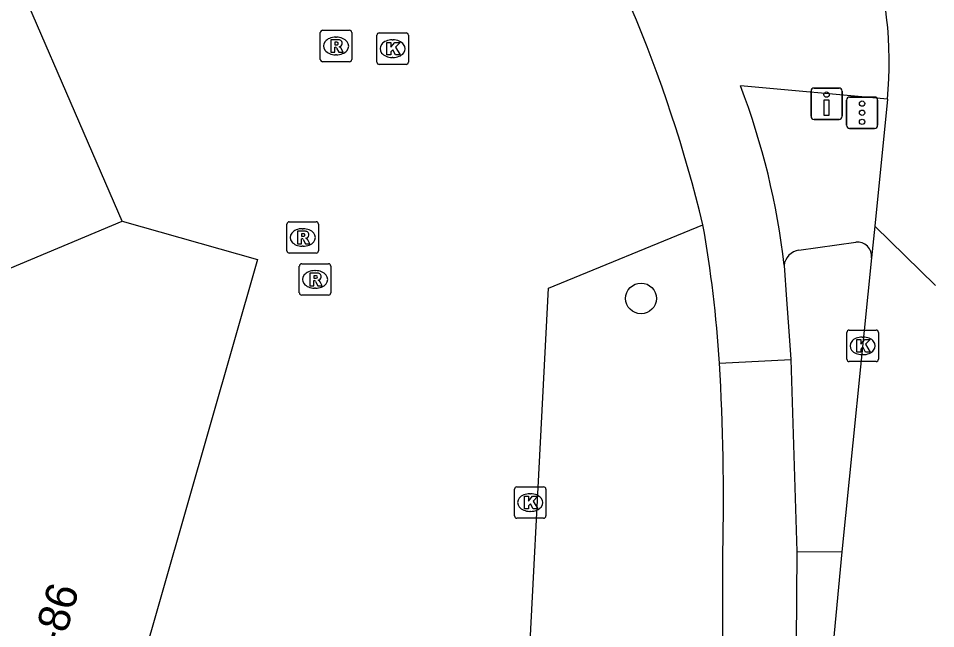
# Model space of a CAD drawing. Extents: x 162542 to 163144, y 380786 to 381511.
# Drawn here: x 163114.67 to 163143.84, y 381201.72 to 381221.15 of the extents above; entities that cross this region are included whole.
import ezdxf

# ---------------------------------------------------------------- set-up
doc = ezdxf.new("R2010")
doc.units = 0
for name, color, linetype in [('IMGEO_Boom', 7, 'Continuous'), ('IMGEO_Drukknoppaal', 7, 'Continuous'), ('IMGEO_Fietspad_gesloten', 7, 'Continuous'), ('IMGEO_Fietspad_open', 7, 'Continuous'), ('IMGEO_Kolk', 7, 'Continuous'), ('IMGEO_Pand', 7, 'Continuous'), ('IMGEO_Pand_nummerreeks', 7, 'Continuous'), ('IMGEO_Rijbaan_lokaal_gesloten', 7, 'Continuous'), ('IMGEO_Rioolput', 7, 'Continuous'), ('IMGEO_Verkeerseiland_open', 7, 'Continuous'), ('IMGEO_Verkeersregelinstallatiepaal', 7, 'Continuous'), ('IMGEO_Voetpad_open', 7, 'Continuous')]:
    doc.layers.add(name, color=color, linetype=linetype)

msp = doc.modelspace()

# ---------------------------------------------------------------- linework, layer by layer
at = {"layer": 'IMGEO_Boom'}
msp.add_circle((163134.469, 381212.234), 0.489, dxfattribs=at)
at = {"layer": 'IMGEO_Drukknoppaal'}
for p, q in [((163139.976, 381218.931), (163140.766, 381218.931)), ((163140.766, 381218.931), (163139.976, 381218.931)), ((163139.876, 381218.031), (163139.876, 381218.831)), ((163139.876, 381218.831), (163139.876, 381218.031)), ((163140.866, 381218.831), (163140.866, 381218.031)), ((163140.866, 381218.031), (163140.866, 381218.831)), ((163140.766, 381217.931), (163139.976, 381217.931)), ((163139.976, 381217.931), (163140.766, 381217.931))]:
    msp.add_line(p, q, dxfattribs=at)
msp.add_lwpolyline([(163140.446, 381218.556), (163140.446, 381218.056), (163140.296, 381218.056), (163140.296, 381218.556), (163140.446, 381218.556)], dxfattribs=at)
msp.add_circle((163140.371, 381218.721), 0.085, dxfattribs=at)
for centre, start, end in [((163139.976, 381218.831), 90, 180), ((163139.976, 381218.831), 90, 180), ((163140.766, 381218.831), 0, 90), ((163140.766, 381218.831), 360, 90), ((163139.976, 381218.031), 180, 270), ((163139.976, 381218.031), 180, 270), ((163140.766, 381218.031), 270, 0), ((163140.766, 381218.031), 270, 0)]:
    msp.add_arc(centre, 0.1, start, end, dxfattribs=at)
at = {"layer": 'IMGEO_Fietspad_gesloten'}
for points in [[(163142.306, 381218.573), (163137.629, 381218.999)], [(163139.017, 381213.288), (163139.096, 381212.197), (163139.171, 381211.191), (163139.237, 381210.292)], [(163136.964, 381210.179), (163139.237, 381210.292)]]:
    msp.add_lwpolyline(points, dxfattribs=at)
for centre, radius, start, end in [((163093.253, 381204.128), 44.432, 13.6085, 32.4494), ((163116.281, 381210.787), 22.873, 6.2787, 21.0419), ((163096.562, 381207.585), 40.485, 3.6731, 9.9519)]:
    msp.add_arc(centre, radius, start, end, dxfattribs=at)
at = {"layer": 'IMGEO_Fietspad_open'}
for points in [[(163139.237, 381210.292), (163139.424, 381204.175)], [(163139.424, 381204.175), (163139.38, 381198.374), (163139.259, 381195.134), (163138.982, 381190.545)]]:
    msp.add_lwpolyline(points, dxfattribs=at)
for centre, radius, start, end in [((163067.009, 381205.966), 70.081, 358.54095, 3.4461), ((162956.403, 381202.847), 180.67, 357.8353, 0.42328)]:
    msp.add_arc(centre, radius, start, end, dxfattribs=at)
at = {"layer": 'IMGEO_Kolk'}
for p, q in [((163126.144, 381220.684), (163126.996, 381220.684)), ((163126.069, 381219.758), (163126.069, 381220.61)), ((163126.557, 381220.464), (163126.582, 381220.464)), ((163127.07, 381220.61), (163127.07, 381219.758)), ((163126.58, 381219.904), (163126.555, 381219.904)), ((163126.996, 381219.684), (163126.144, 381219.684)), ((163141.016, 381210.3), (163141.016, 381211.152)), ((163141.091, 381211.226), (163141.943, 381211.226)), ((163141.504, 381211.006), (163141.529, 381211.006)), ((163142.017, 381211.152), (163142.017, 381210.3)), ((163141.527, 381210.446), (163141.502, 381210.446)), ((163141.943, 381210.226), (163141.091, 381210.226)), ((163130.445, 381205.312), (163130.445, 381206.164)), ((163130.52, 381206.238), (163131.372, 381206.238)), ((163131.446, 381206.164), (163131.446, 381205.312)), ((163130.933, 381206.018), (163130.958, 381206.018)), ((163131.372, 381205.238), (163130.52, 381205.238)), ((163130.956, 381205.458), (163130.931, 381205.458))]:
    msp.add_line(p, q, dxfattribs=at)
for points in [[(163126.144, 381220.684), (163126.996, 381220.684)], [(163126.069, 381219.758), (163126.069, 381220.61)], [(163126.39, 381220.384), (163126.513, 381220.384), (163126.513, 381220.233), (163126.643, 381220.384), (163126.807, 381220.384), (163126.661, 381220.233), (163126.814, 381219.984), (163126.662, 381219.984), (163126.577, 381220.148), (163126.513, 381220.081), (163126.513, 381219.984), (163126.39, 381219.984), (163126.39, 381220.384)], [(163127.07, 381220.61), (163127.07, 381219.758)], [(163126.996, 381219.684), (163126.144, 381219.684)], [(163141.016, 381210.3), (163141.016, 381211.152)], [(163141.091, 381211.226), (163141.943, 381211.226)], [(163142.017, 381211.152), (163142.017, 381210.3)], [(163141.337, 381210.926), (163141.46, 381210.926), (163141.46, 381210.775), (163141.59, 381210.926), (163141.754, 381210.926), (163141.608, 381210.775), (163141.761, 381210.526), (163141.609, 381210.526), (163141.524, 381210.69), (163141.46, 381210.623), (163141.46, 381210.526), (163141.337, 381210.526), (163141.337, 381210.926)], [(163141.943, 381210.226), (163141.091, 381210.226)], [(163130.445, 381205.312), (163130.445, 381206.164)], [(163130.52, 381206.238), (163131.372, 381206.238)], [(163131.446, 381206.164), (163131.446, 381205.312)], [(163130.766, 381205.938), (163130.889, 381205.938), (163130.889, 381205.787), (163131.019, 381205.938), (163131.183, 381205.938), (163131.037, 381205.787), (163131.19, 381205.538), (163131.038, 381205.538), (163130.953, 381205.702), (163130.889, 381205.635), (163130.889, 381205.538), (163130.766, 381205.538), (163130.766, 381205.938)], [(163131.372, 381205.238), (163130.52, 381205.238)]]:
    msp.add_lwpolyline(points, dxfattribs=at)
for centre, start, end in [((163126.146, 381220.608), 91.552, 178.448), ((163126.146, 381220.608), 91.552, 178.448), ((163126.994, 381220.608), 1.552, 88.448), ((163126.994, 381220.608), 1.552, 88.448), ((163126.146, 381219.76), 181.552, 268.448), ((163126.146, 381219.76), 181.552, 268.448), ((163126.994, 381219.76), 271.552, 358.448), ((163126.994, 381219.76), 271.552, 358.448), ((163141.093, 381211.15), 91.552, 178.448), ((163141.093, 381211.15), 91.552, 178.448), ((163141.941, 381211.15), 1.552, 88.448), ((163141.941, 381211.15), 1.552, 88.448), ((163141.093, 381210.302), 181.552, 268.448), ((163141.093, 381210.302), 181.552, 268.448), ((163141.941, 381210.302), 271.552, 358.448), ((163141.941, 381210.302), 271.552, 358.448), ((163130.522, 381206.162), 91.552, 178.448), ((163130.522, 381206.162), 91.552, 178.448), ((163131.37, 381206.162), 1.552, 88.448), ((163131.37, 381206.162), 1.552, 88.448), ((163130.522, 381205.314), 181.552, 268.448), ((163130.522, 381205.314), 181.552, 268.448), ((163131.37, 381205.314), 271.552, 358.448), ((163131.37, 381205.314), 271.552, 358.448)]:
    msp.add_arc(centre, 0.0765, start, end, dxfattribs=at)
for centre, major_axis, ratio, start_param, end_param in [((163126.556, 381220.184), (-0.387, 0.002), 0.722429, 4.712389, 7.853982), ((163126.581, 381220.184), (-0.39, 0.002), 0.717154, 1.570796, 4.712389), ((163141.503, 381210.726), (-0.387, 0.002), 0.722429, 4.712389, 7.853982), ((163141.528, 381210.726), (-0.39, 0.002), 0.717154, 1.570796, 4.712389), ((163130.932, 381205.738), (-0.387, 0.002), 0.722429, 4.712389, 7.853982), ((163130.957, 381205.738), (-0.39, 0.002), 0.717154, 1.570796, 4.712389)]:
    msp.add_ellipse(centre, major_axis=major_axis, ratio=ratio, start_param=start_param, end_param=end_param, dxfattribs=at)
at = {"layer": 'IMGEO_Pand'}
for points in [[(163085.066, 381198.411), (163084.14, 381200.482), (163108.916, 381210.892), (163117.973, 381214.696)], [(163117.973, 381214.696), (163122.273, 381213.473), (163115.473, 381189.724)]]:
    msp.add_lwpolyline(points, dxfattribs=at)
at = {"layer": 'IMGEO_Rijbaan_lokaal_gesloten'}
for points in [[(163142.306, 381218.573), (163141.902, 381214.535)], [(163141.902, 381214.535), (163141.801, 381213.528)], [(163143.838, 381212.646), (163141.902, 381214.535)], [(163141.801, 381213.528), (163140.853, 381204.171)], [(163140.853, 381204.171), (163140.26, 381197.872), (163139.77, 381190.501)]]:
    msp.add_lwpolyline(points, dxfattribs=at)
msp.add_arc((163129.901, 381219.755), 12.461, 354.5553, 18.5621, dxfattribs=at)
at = {"layer": 'IMGEO_Rioolput'}
for p, q in [((163124.27, 381219.843), (163124.27, 381220.695)), ((163124.345, 381220.769), (163125.197, 381220.769)), ((163125.271, 381220.695), (163125.271, 381219.843)), ((163124.758, 381220.549), (163124.783, 381220.549)), ((163125.197, 381219.769), (163124.345, 381219.769)), ((163124.781, 381219.989), (163124.756, 381219.989)), ((163123.21, 381213.749), (163123.21, 381214.601)), ((163123.285, 381214.675), (163124.137, 381214.675)), ((163124.211, 381214.601), (163124.211, 381213.749)), ((163123.698, 381214.455), (163123.723, 381214.455)), ((163124.137, 381213.675), (163123.285, 381213.675)), ((163123.721, 381213.895), (163123.696, 381213.895)), ((163123.678, 381213.34), (163124.53, 381213.34)), ((163123.603, 381212.414), (163123.603, 381213.266)), ((163124.091, 381213.12), (163124.116, 381213.12)), ((163124.604, 381213.266), (163124.604, 381212.414)), ((163124.114, 381212.56), (163124.089, 381212.56)), ((163124.53, 381212.34), (163123.678, 381212.34))]:
    msp.add_line(p, q, dxfattribs=at)
for points in [[(163124.27, 381219.843), (163124.27, 381220.695)], [(163124.345, 381220.769), (163125.197, 381220.769)], [(163125.271, 381220.695), (163125.271, 381219.843)], [(163124.859, 381220.467), (163124.607, 381220.469), (163124.607, 381220.069)], [(163124.785, 381220.388), (163124.731, 381220.388), (163124.731, 381220.307)], [(163124.607, 381220.069), (163124.731, 381220.069), (163124.731, 381220.231), (163124.742, 381220.231)], [(163124.731, 381220.307), (163124.783, 381220.307)], [(163124.789, 381220.202), (163124.86, 381220.069), (163125, 381220.069), (163124.935, 381220.195)], [(163125.197, 381219.769), (163124.345, 381219.769)], [(163123.21, 381213.749), (163123.21, 381214.601)], [(163123.285, 381214.675), (163124.137, 381214.675)], [(163124.211, 381214.601), (163124.211, 381213.749)], [(163123.799, 381214.373), (163123.547, 381214.375), (163123.547, 381213.975)], [(163123.725, 381214.294), (163123.671, 381214.294), (163123.671, 381214.213)], [(163123.547, 381213.975), (163123.671, 381213.975), (163123.671, 381214.137), (163123.682, 381214.137)], [(163123.671, 381214.213), (163123.723, 381214.213)], [(163123.729, 381214.108), (163123.8, 381213.975), (163123.94, 381213.975), (163123.875, 381214.101)], [(163124.137, 381213.675), (163123.285, 381213.675)], [(163123.678, 381213.34), (163124.53, 381213.34)], [(163123.603, 381212.414), (163123.603, 381213.266)], [(163124.604, 381213.266), (163124.604, 381212.414)], [(163124.192, 381213.038), (163123.94, 381213.04), (163123.94, 381212.64)], [(163123.94, 381212.64), (163124.064, 381212.64), (163124.064, 381212.802), (163124.075, 381212.802)], [(163124.118, 381212.959), (163124.064, 381212.959), (163124.064, 381212.878)], [(163124.064, 381212.878), (163124.116, 381212.878)], [(163124.122, 381212.773), (163124.193, 381212.64), (163124.333, 381212.64), (163124.268, 381212.766)], [(163124.53, 381212.34), (163123.678, 381212.34)]]:
    msp.add_lwpolyline(points, dxfattribs=at)
for centre, radius, start, end in [((163124.347, 381220.693), 0.0765, 91.552, 178.448), ((163124.347, 381220.693), 0.0765, 91.552, 178.448), ((163125.195, 381220.693), 0.0765, 1.552, 88.448), ((163125.195, 381220.693), 0.0765, 1.552, 88.448), ((163124.791, 381220.292), 0.0964, 77.0061, 93.1865), ((163124.805, 381220.349), 0.0378, 276.6634, 79.6772), ((163124.858, 381220.357), 0.109, 350.3612, 89.416), ((163124.741, 381220.178), 0.0533, 26.0293, 88.6989), ((163124.767, 381220.496), 0.19, 274.7715, 282.9687), ((163124.856, 381220.357), 0.112, 277.5842, 350.9817), ((163124.84, 381220.142), 0.108, 29.5134, 73.7905), ((163124.347, 381219.845), 0.0765, 181.552, 268.448), ((163124.347, 381219.845), 0.0765, 181.552, 268.448), ((163125.195, 381219.845), 0.0765, 271.552, 358.448), ((163125.195, 381219.845), 0.0765, 271.552, 358.448), ((163123.287, 381214.599), 0.0765, 91.552, 178.448), ((163123.287, 381214.599), 0.0765, 91.552, 178.448), ((163124.135, 381214.599), 0.0765, 1.552, 88.448), ((163124.135, 381214.599), 0.0765, 1.552, 88.448), ((163123.707, 381214.402), 0.19, 274.7715, 282.9687), ((163123.731, 381214.198), 0.0964, 77.0061, 93.1865), ((163123.745, 381214.255), 0.0378, 276.6634, 79.6772), ((163123.798, 381214.263), 0.109, 350.3612, 89.416), ((163123.796, 381214.263), 0.112, 277.5842, 350.9817), ((163123.681, 381214.084), 0.0533, 26.0293, 88.6989), ((163123.78, 381214.048), 0.108, 29.5134, 73.7905), ((163123.287, 381213.751), 0.0765, 181.552, 268.448), ((163123.287, 381213.751), 0.0765, 181.552, 268.448), ((163124.135, 381213.751), 0.0765, 271.552, 358.448), ((163124.135, 381213.751), 0.0765, 271.552, 358.448), ((163123.68, 381213.264), 0.0765, 91.552, 178.448), ((163123.68, 381213.264), 0.0765, 91.552, 178.448), ((163124.528, 381213.264), 0.0765, 1.552, 88.448), ((163124.528, 381213.264), 0.0765, 1.552, 88.448), ((163124.074, 381212.749), 0.0533, 26.0293, 88.6989), ((163124.1, 381213.067), 0.19, 274.7715, 282.9687), ((163124.124, 381212.863), 0.0964, 77.0061, 93.1865), ((163124.138, 381212.92), 0.0378, 276.6634, 79.6772), ((163124.191, 381212.928), 0.109, 350.3612, 89.416), ((163124.189, 381212.928), 0.112, 277.5842, 350.9817), ((163124.173, 381212.713), 0.108, 29.5134, 73.7905), ((163123.68, 381212.416), 0.0765, 181.552, 268.448), ((163123.68, 381212.416), 0.0765, 181.552, 268.448), ((163124.528, 381212.416), 0.0765, 271.552, 358.448), ((163124.528, 381212.416), 0.0765, 271.552, 358.448)]:
    msp.add_arc(centre, radius, start, end, dxfattribs=at)
for centre, major_axis, ratio, start_param, end_param in [((163124.757, 381220.269), (-0.387, 0.002), 0.722429, 4.712389, 7.853982), ((163124.782, 381220.269), (-0.39, 0.002), 0.717154, 1.570796, 4.712389), ((163123.697, 381214.175), (-0.387, 0.002), 0.722429, 4.712389, 7.853982), ((163123.722, 381214.175), (-0.39, 0.002), 0.717154, 1.570796, 4.712389), ((163124.09, 381212.84), (-0.387, 0.002), 0.722429, 4.712389, 7.853982), ((163124.115, 381212.84), (-0.39, 0.002), 0.717154, 1.570796, 4.712389)]:
    msp.add_ellipse(centre, major_axis=major_axis, ratio=ratio, start_param=start_param, end_param=end_param, dxfattribs=at)
at = {"layer": 'IMGEO_Verkeerseiland_open'}
msp.add_lwpolyline([(163139.424, 381204.175), (163140.853, 381204.171)], dxfattribs=at)
at = {"layer": 'IMGEO_Verkeersregelinstallatiepaal'}
for p, q in [((163141.103, 381218.646), (163141.893, 381218.646)), ((163141.893, 381218.646), (163141.103, 381218.646)), ((163141.003, 381217.746), (163141.003, 381218.546)), ((163141.003, 381218.546), (163141.003, 381217.746)), ((163141.993, 381218.546), (163141.993, 381217.746)), ((163141.993, 381217.746), (163141.993, 381218.546)), ((163141.893, 381217.646), (163141.103, 381217.646)), ((163141.103, 381217.646), (163141.893, 381217.646))]:
    msp.add_line(p, q, dxfattribs=at)
for centre in [(163141.498, 381218.436), (163141.498, 381218.146), (163141.498, 381217.856)]:
    msp.add_circle(centre, 0.085, dxfattribs=at)
for centre, start, end in [((163141.103, 381218.546), 90, 180), ((163141.103, 381218.546), 90, 180), ((163141.893, 381218.546), 0, 90), ((163141.893, 381218.546), 360, 90), ((163141.103, 381217.746), 180, 270), ((163141.103, 381217.746), 180, 270), ((163141.893, 381217.746), 270, 0), ((163141.893, 381217.746), 270, 0)]:
    msp.add_arc(centre, 0.1, start, end, dxfattribs=at)
at = {"layer": 'IMGEO_Voetpad_open'}
for points in [[(163117.973, 381214.696), (163113.474, 381225.063)], [(163136.944, 381196.023), (163130.687, 381196.388), (163131.523, 381212.564), (163136.438, 381214.582)], [(163139.489, 381213.772), (163141.302, 381214.028)]]:
    msp.add_lwpolyline(points, dxfattribs=at)
for centre, radius, start, end in [((163141.341, 381213.568), 0.461, 354.9898, 94.8955), ((163139.572, 381213.219), 0.559, 98.5432, 172.8951)]:
    msp.add_arc(centre, radius, start, end, dxfattribs=at)

# ---------------------------------------------------------------- texts
at = {"layer": 'IMGEO_Pand_nummerreeks'}
msp.add_text('8-86', height=1, rotation=73.7634, dxfattribs=at).set_placement((163115.862, 381200.411))

doc.saveas('drawing.dxf')
